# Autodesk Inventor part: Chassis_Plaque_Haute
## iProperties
Created: 2009-01
Part Number: Chassis_Plaque_Haute
Document SubType Name: Sheet Metal
Designer: claivier
Author: claivier
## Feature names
1. Perçage1 [Hole]
2. Perçage2 [Hole]
3. Perçage3 [Hole]
4. Perçage4 [Hole]
5. Perçage5 [Hole]
6. Perçage6 [Hole]
7. Extrusion1
8. Extrusion2
9. Chanfrein de coin1
10. Chanfrein de coin2
11. Perçage7 [Hole]
12. Miroir1 [Mirror]
13. Plaque1
14. Pli1
15. Couper1
16. Couper2
